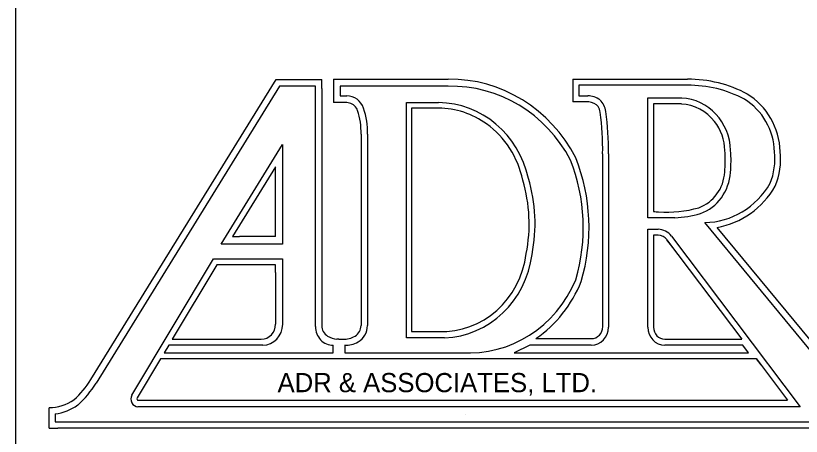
# Model space of a CAD drawing. Extents: x 0 to 2329303, y 0 to 694397.
# Drawn here: x 32 to 33.31, y 3.463 to 4.165 of the extents above; entities that cross this region are included whole.
import ezdxf

# ---------------------------------------------------------------- set-up
doc = ezdxf.new("R2010")
doc.units = 0
doc.layers.add('SH_Border', color=7, linetype='Continuous')
doc.layers.add('SH_Data', color=7, linetype='Continuous')

msp = doc.modelspace()

# ---------------------------------------------------------------- linework, layer by layer
at = {"layer": 'SH_Border'}
msp.add_line((32, 0.5), (32, 21.5), dxfattribs=at)
at = {"layer": 'SH_Data'}
for p, q in [((32.1254, 3.558), (32.4341, 4.0584)), ((32.4341, 4.0584), (32.5101, 4.0584)), ((32.5101, 4.0435), (32.5101, 4.0584)), ((32.53, 4.059), (32.53, 4.02)), ((32.53, 4.059), (32.721, 4.059)), ((32.929, 4.059), (32.929, 4.0215)), ((32.929, 4.059), (33.12, 4.059)), ((32.929, 4.059), (32.929, 4.0215)), ((32.929, 4.059), (33.12, 4.059)), ((32.5101, 4.0435), (32.5101, 3.6481)), ((32.9432, 4.0215), (32.929, 4.0215)), ((32.9432, 4.0215), (32.929, 4.0215)), ((32.951, 4.0215), (32.9432, 4.0215)), ((32.5442, 4.02), (32.53, 4.02)), ((32.552, 4.02), (32.5442, 4.02)), ((32.7049, 4.011), (32.6598, 4.011)), ((32.6598, 4.011), (32.6598, 3.6379)), ((32.5757, 3.9673), (32.5757, 3.6481)), ((32.9785, 3.6462), (32.9785, 3.9347)), ((32.4331, 3.9128), (32.3615, 3.7966)), ((32.4331, 3.8944), (32.4331, 3.9128)), ((32.4331, 3.7966), (32.4331, 3.8944)), ((33.3849, 3.5506), (33.1692, 3.8119)), ((32.3615, 3.7966), (32.3728, 3.7966)), ((32.4331, 3.7966), (32.3728, 3.7966)), ((33.0868, 3.7896), (33.2106, 3.6252)), ((32.3351, 3.7491), (32.2609, 3.6252)), ((32.4331, 3.7491), (32.3351, 3.7491)), ((32.4331, 3.7366), (32.4331, 3.7491)), ((32.4331, 3.7366), (32.4331, 3.6502)), ((32.6598, 3.6379), (32.6683, 3.6379)), ((32.6683, 3.6379), (32.7049, 3.6379)), ((32.2609, 3.6252), (32.2722, 3.6252)), ((32.2722, 3.6252), (32.4094, 3.6252)), ((32.5384, 3.6252), (32.5356, 3.6254)), ((32.5384, 3.6252), (32.5356, 3.6254)), ((32.5384, 3.6252), (32.5453, 3.6252)), ((32.8673, 3.6262), (32.9595, 3.6262)), ((33.0822, 3.6252), (33.2106, 3.6252)), ((33.2351, 3.5922), (33.2867, 3.5234)), ((32.2043, 3.5234), (32.2112, 3.5234)), ((32.2112, 3.5234), (33.2867, 3.5234)), ((32.0556, 3.4766), (32.0556, 3.5109)), ((32.75, 3.5), (32.75, 3.5)), ((32.0556, 3.4766), (32.0701, 3.4766)), ((33.4404, 3.4766), (32.0701, 3.4766))]:
    msp.add_line(p, q, dxfattribs=at)
for points in [[(32.4996, 3.6463), (32.4996, 4.0474), (32.4398, 4.0474), (32.1341, 3.552)], [(32.721, 4.0474), (32.541, 4.0474), (32.541, 4.0313), (32.552, 4.0313)], [(33.12, 4.049), (32.9385, 4.049), (32.9385, 4.0315), (32.9536, 4.0315)], [(33.0537, 4.0278), (33.1102, 4.0278)], [(33.0987, 3.8276), (33.0537, 3.8276), (33.0537, 4.0278)], [(32.6514, 3.6276), (32.6514, 4.02), (32.7049, 4.02)], [(33.11, 4.0178), (33.0632, 4.0178), (33.0632, 3.8384)], [(32.5864, 3.9673), (32.5864, 3.9668), (32.5864, 3.6481)], [(32.445, 3.7841), (32.3424, 3.7841), (32.445, 3.9504), (32.445, 3.7841)], [(32.988, 3.9346), (32.988, 3.6452)], [(33.3772, 3.5431), (33.1487, 3.82)], [(33.0537, 3.6452), (33.0537, 3.8086), (33.0709, 3.8086)], [(33.0709, 3.7986), (33.0632, 3.7986), (33.0632, 3.6452)], [(33.0932, 3.7972), (33.3075, 3.5126), (32.2038, 3.5126)], [(33.0954, 3.7782), (33.0857, 3.791)], [(32.1938, 3.5318), (32.3298, 3.7591), (32.445, 3.7591), (32.445, 3.6502)], [(32.4118, 3.6152), (32.2551, 3.6152), (32.2476, 3.6027), (32.5292, 3.6027), (32.5292, 3.6152)], [(32.5484, 3.6152), (32.5484, 3.6027), (32.7432, 3.6027)], [(32.715, 3.6276), (32.6514, 3.6276)], [(32.9595, 3.6152), (32.857, 3.6152), (32.8311, 3.6027), (33.2217, 3.6027), (33.2123, 3.6152), (33.0822, 3.6152)], [(32.8673, 3.6262), (32.8894, 3.6262)], [(33.0822, 3.6252), (33.086, 3.6252)], [(33.2426, 3.5822), (33.2351, 3.5922), (32.2412, 3.5922), (32.2022, 3.5272)], [(32.066, 3.5006), (32.066, 3.4876), (33.4299, 3.4876), (33.4299, 3.5006)]]:
    msp.add_lwpolyline(points, dxfattribs=at)
for centre, major_axis, start_param, end_param in [((32.7243, 3.8082), (0, 0.2509), 5.209873, 6.297313), ((32.726, 3.8081), (0, 0.2394), 5.218006, 6.305445), ((33.1223, 3.8329), (0, 0.2261), 5.810103, 6.294452), ((33.1223, 3.8329), (0, 0.2261), 5.810103, 6.294452), ((33.1224, 3.8335), (0, 0.2155), 5.814829, 6.29527), ((33.1638, 3.9336), (0, 0.1167), 4.753214, 5.755325), ((33.1638, 3.9336), (0, 0.1167), 4.753214, 5.755325), ((32.552, 4), (0, 0.0313), 5.060756, 6.283185), ((32.9522, 3.9897), (0, 0.0318), 5.717883, 6.322951), ((32.9522, 3.9897), (0, 0.0418), 5.696071, 6.248499), ((32.9551, 4.0016), (0, 0.0304), 4.832872, 5.561833), ((33.1063, 3.9378), (0, 0.09), 4.740194, 6.23721), ((33.1638, 3.9336), (0, 0.1067), 4.750292, 5.755325), ((32.552, 4), (0, 0.02), 5.294753, 6.283185), ((32.552, 4), (0, 0.02), 5.060756, 5.294753), ((32.4775, 3.9716), (0, 0.1147), 4.675194, 5.060756), ((32.7039, 3.8572), (0, 0.1628), 4.938334, 6.276888), ((32.7028, 3.8574), (0, 0.1537), 5.684676, 6.268828), ((32.9551, 4.0016), (0, 0.0204), 5.34604, 5.529903), ((32.9551, 4.0016), (0, 0.0204), 4.827568, 5.34604), ((32.9551, 4.0016), (0, 0.0204), 4.827568, 5.34604), ((33.1063, 3.9378), (0, 0.08), 5.402738, 6.234422), ((32.4775, 3.9716), (0, 0.1034), 4.671123, 5.060756), ((32.5748, 3.9427), (0, 0.425), 4.693619, 4.857063), ((32.5748, 3.9427), (0, 0.425), 4.693619, 4.857063), ((32.5748, 3.9427), (0, 0.435), 4.693836, 4.856756), ((32.7028, 3.8574), (0, 0.1537), 4.930275, 5.684676), ((33.1063, 3.9378), (0, 0.08), 4.740194, 5.402738), ((33.1063, 3.9378), (0, 0.08), 4.740194, 5.402738), ((33.0035, 3.9239), (0, 0.1889), 4.608112, 4.797709), ((33.0035, 3.9239), (0, 0.1889), 4.608112, 4.797709), ((33.0086, 3.9238), (0, 0.1936), 4.607961, 4.797558), ((33.166, 3.9266), (0, 0.1049), 4.309756, 4.818512), ((33.166, 3.9266), (0, 0.1149), 4.303317, 4.815541), ((33.166, 3.9266), (0, 0.1149), 4.303317, 4.815541), ((32.6675, 3.8117), (0, 0.2934), 4.410917, 5.105556), ((32.6675, 3.8117), (0, 0.3034), 4.410917, 5.105556), ((33.1182, 3.9083), (0, -0.0672), 0.330696, 1.511334), ((33.1182, 3.9083), (0, -0.0672), 0.330696, 1.511334), ((33.1178, 3.9086), (0, -0.0777), 0.32607, 1.506707), ((32.6246, 3.8176), (0, 0.2435), 4.507644, 5.016706), ((32.626, 3.8177), (0, 0.2524), 4.509144, 5.018206), ((33.1467, 3.957), (0, -0.1371), 0.015856, 1.021186), ((33.1467, 3.957), (0, -0.1471), 0.16231, 1.026165), ((33.1467, 3.957), (0, -0.1471), 0.16231, 1.026165), ((33.0851, 4.056), (0, -0.2188), 6.177822, 6.219099), ((33.0851, 4.056), (0, -0.2188), 6.219099, 6.545404), ((33.0851, 4.056), (0, -0.2188), 6.219099, 6.545404), ((33.0851, 4.056), (0, -0.2288), 0.06267, 0.262218), ((33.0709, 3.7786), (0, 0.03), 5.382662, 6.283185), ((33.0709, 3.7786), (0, 0.02), 5.382662, 6.283185), ((32.7099, 3.7877), (0, -0.1499), 6.247489, 7.723), ((32.7099, 3.7877), (0, -0.1602), 0.033392, 1.439815), ((32.7557, 3.807), (0, -0.2047), 6.218561, 7.439351), ((32.7556, 3.8048), (0, -0.2139), 0.582172, 1.170799), ((32.4094, 3.6502), (0, -0.025), 0, 1.570796), ((32.4118, 3.6502), (0, -0.035), 0, 1.570796), ((32.5292, 3.6463), (0, -0.0311), 4.712389, 6.28383), ((32.5291, 3.6481), (0, -0.02), 4.712389, 5.785309), ((32.5567, 3.6481), (0, -0.02), 0.497877, 1.570796), ((32.5567, 3.6481), (0, -0.0313), 0.497877, 1.570796), ((32.9595, 3.6462), (0, -0.02), 0, 1.570796), ((32.9595, 3.6452), (0, -0.03), 0, 1.570796), ((33.0822, 3.6452), (0, -0.03), 4.712389, 6.283185), ((33.0822, 3.6452), (0, -0.02), 4.712389, 6.283185), ((32.5401, 3.6695), (0, -0.0444), 5.785308, 6.174936), ((32.5456, 3.6695), (0, -0.0444), 6.276852, 6.781063), ((32.5506, 3.6599), (0, -0.0447), 6.230381, 6.780961), ((31.9988, 3.6451), (0, -0.1592), 0.707735, 0.991966), ((31.9988, 3.6451), (0, -0.1702), 0.704048, 0.991966), ((32.0559, 3.5887), (0, -0.0777), 6.278764, 6.875053), ((32.2038, 3.5251), (0, -0.0125), 4.150117, 6.283185), ((32.2043, 3.5259), (0, -0.0025), 4.150111, 6.283185), ((32.0559, 3.5887), (0, -0.0887), 0.120377, 0.599173)]:
    msp.add_ellipse(centre, major_axis=major_axis, ratio=0.95, start_param=start_param, end_param=end_param, dxfattribs=at)

# ---------------------------------------------------------------- texts
msp.add_text('ADR & ASSOCIATES, LTD.', height=0.032, dxfattribs=at).set_placement((32.4365, 3.5368))

doc.saveas('drawing.dxf')
